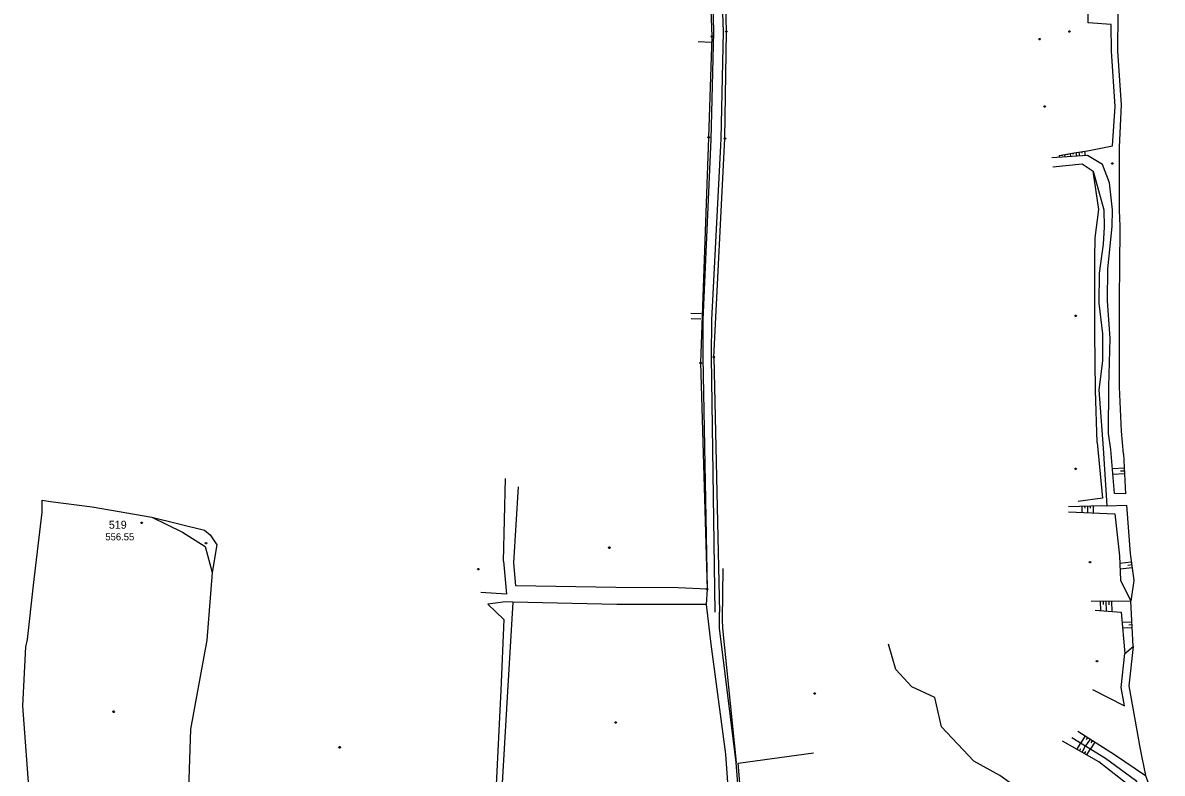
# Model space of a CAD drawing. Extents: x -664960 to -662754, y -993849 to -991145.
# Drawn here: x -664427.2 to -663943.3, y -992059.4 to -991740.8 of the extents above; entities that cross this region are included whole.
import ezdxf

# ---------------------------------------------------------------- set-up
doc = ezdxf.new("R2010")
doc.units = 0
for name, color, linetype in [('Vrstva 1', 7, 'Continuous'), ('Vrstva 12', 7, 'Continuous'), ('Vrstva 13', 7, 'Continuous'), ('Vrstva 18', 7, 'Continuous'), ('Vrstva 27', 7, 'Continuous'), ('Vrstva 28', 7, 'Continuous'), ('Vrstva 6', 7, 'Continuous'), ('Vrstva 63', 7, 'Continuous'), ('Vrstva 8', 7, 'Continuous')]:
    doc.layers.add(name, color=color, linetype=linetype)

msp = doc.modelspace()

# ---------------------------------------------------------------- linework, layer by layer
at = {"layer": 'Vrstva 12'}
msp.add_lwpolyline([(-664087.76, -992082.088), (-664120.622, -992086.914), (-664123.342, -992055.125), (-664091.387, -992050.694)], dxfattribs=at)
at = {"layer": 'Vrstva 13'}
for points in [[(-663993.028, -991776.032), (-663992.848, -991776.332), (-663993.028, -991776.632), (-663993.388, -991776.632), (-663993.568, -991776.332), (-663993.388, -991776.032), (-663993.028, -991776.032)], [(-663964.255, -991800.227), (-663964.075, -991800.527), (-663964.255, -991800.827), (-663964.615, -991800.827), (-663964.795, -991800.527), (-663964.615, -991800.227), (-663964.255, -991800.227)], [(-663979.838, -991864.893), (-663979.658, -991865.193), (-663979.838, -991865.493), (-663980.198, -991865.493), (-663980.378, -991865.193), (-663980.198, -991864.893), (-663979.838, -991864.893)], [(-663979.848, -991929.914), (-663979.668, -991930.214), (-663979.848, -991930.514), (-663980.208, -991930.514), (-663980.388, -991930.214), (-663980.208, -991929.914), (-663979.848, -991929.914)], [(-664349.219, -991961.406), (-664349.039, -991961.706), (-664349.219, -991962.006), (-664349.579, -991962.006), (-664349.759, -991961.706), (-664349.579, -991961.406), (-664349.219, -991961.406)], [(-664177.878, -991963.344), (-664177.698, -991963.644), (-664177.878, -991963.944), (-664178.238, -991963.944), (-664178.418, -991963.644), (-664178.238, -991963.344), (-664177.878, -991963.344)], [(-663973.789, -991969.535), (-663973.609, -991969.835), (-663973.789, -991970.135), (-663974.149, -991970.135), (-663974.329, -991969.835), (-663974.149, -991969.535), (-663973.789, -991969.535)], [(-664233.506, -991972.423), (-664233.326, -991972.723), (-664233.506, -991973.023), (-664233.866, -991973.023), (-664234.046, -991972.723), (-664233.866, -991972.423), (-664233.506, -991972.423)], [(-663970.759, -992011.486), (-663970.579, -992011.786), (-663970.759, -992012.086), (-663971.119, -992012.086), (-663971.299, -992011.786), (-663971.119, -992011.486), (-663970.759, -992011.486)], [(-664090.692, -992025.293), (-664090.512, -992025.593), (-664090.692, -992025.893), (-664091.052, -992025.893), (-664091.232, -992025.593), (-664091.052, -992025.293), (-664090.692, -992025.293)], [(-664388.454, -992032.938), (-664388.274, -992033.238), (-664388.454, -992033.538), (-664388.814, -992033.538), (-664388.994, -992033.238), (-664388.814, -992032.938), (-664388.454, -992032.938)], [(-664175.204, -992037.575), (-664175.024, -992037.875), (-664175.204, -992038.175), (-664175.564, -992038.175), (-664175.744, -992037.875), (-664175.564, -992037.575), (-664175.204, -992037.575)], [(-664292.398, -992048.101), (-664292.218, -992048.401), (-664292.398, -992048.701), (-664292.758, -992048.701), (-664292.938, -992048.401), (-664292.758, -992048.101), (-664292.398, -992048.101)]]:
    msp.add_lwpolyline(points, dxfattribs=at)
at = {"layer": 'Vrstva 18'}
for points in [[(-663995.174, -991747.477), (-663994.994, -991747.777), (-663995.174, -991748.077), (-663995.534, -991748.077), (-663995.714, -991747.777), (-663995.534, -991747.477), (-663995.174, -991747.477)], [(-663982.476, -991744.236), (-663982.296, -991744.536), (-663982.476, -991744.836), (-663982.836, -991744.836), (-663983.016, -991744.536), (-663982.836, -991744.236), (-663982.476, -991744.236)], [(-664136.38, -991980.94), (-664136.2, -991981.24), (-664136.38, -991981.54), (-664136.74, -991981.54), (-664136.92, -991981.24), (-664136.74, -991980.94), (-664136.38, -991980.94)]]:
    msp.add_lwpolyline(points, dxfattribs=at)
at = {"layer": 'Vrstva 27'}
for p, q in [((-664133.69, -991882.79), (-664131.26, -991990.95)), ((-664139.31, -991885.24), (-664136.56, -991981.24))]:
    msp.add_line(p, q, dxfattribs=at)
for points in [[(-664133.76, -991622.74), (-664136.26, -991701.13), (-664134.54, -991746.66), (-664135.91, -991789.46), (-664139.31, -991885.24)], [(-664133.69, -991882.79), (-664128.98, -991790), (-664128.35, -991744.5), (-664129.62, -991693.99), (-664126.2, -991623.19)], [(-664134.36, -991746.36), (-664134.18, -991746.66), (-664134.36, -991746.96), (-664134.72, -991746.96), (-664134.9, -991746.66), (-664134.72, -991746.36), (-664134.36, -991746.36)], [(-664128.17, -991744.2), (-664127.99, -991744.5), (-664128.17, -991744.8), (-664128.53, -991744.8), (-664128.71, -991744.5), (-664128.53, -991744.2), (-664128.17, -991744.2)], [(-664135.73, -991789.16), (-664135.55, -991789.46), (-664135.73, -991789.76), (-664136.09, -991789.76), (-664136.27, -991789.46), (-664136.09, -991789.16), (-664135.73, -991789.16)], [(-664128.8, -991789.7), (-664128.62, -991790), (-664128.8, -991790.3), (-664129.16, -991790.3), (-664129.34, -991790), (-664129.16, -991789.7), (-664128.8, -991789.7)], [(-663965.081, -991921.967), (-663966.071, -991915.134), (-663965.899, -991895.174), (-663965.394, -991874.877), (-663966.498, -991858.814), (-663966.3, -991845.24), (-663964.466, -991827.329), (-663964.397, -991820.302), (-663965.695, -991808.804), (-663968.679, -991800.982), (-663975.044, -991797.204), (-663990.208, -991798.159)], [(-663989.715, -991801.952), (-663977.282, -991800.747), (-663972.626, -991803.762), (-663968.037, -991820.234), (-663967.857, -991827.623), (-663968.372, -991834.776), (-663969.969, -991847.156), (-663970.144, -991859.834), (-663968.66, -991872.81), (-663968.654, -991884.271), (-663970.24, -991896.577), (-663968.403, -991921.366)], [(-664133.51, -991882.49), (-664133.33, -991882.79), (-664133.51, -991883.09), (-664133.87, -991883.09), (-664134.05, -991882.79), (-664133.87, -991882.49), (-664133.51, -991882.49)], [(-664139.13, -991884.94), (-664138.95, -991885.24), (-664139.13, -991885.54), (-664139.49, -991885.54), (-664139.67, -991885.24), (-664139.49, -991884.94), (-664139.13, -991884.94)], [(-663968.403, -991921.366), (-663966.74, -991945.879), (-663958.425, -991945.59)], [(-663958.913, -991940.781), (-663963.592, -991940.621), (-663965.081, -991921.967)], [(-664136.56, -991981.24), (-664136.89, -991987.76), (-664134.9, -992004.59), (-664128.78, -992051.29), (-664125.55, -992095.45), (-664123.48, -992115.18), (-664118.48, -992141.38), (-664113.62, -992159.36), (-664110.38, -992176.55), (-664109.39, -992189.71), (-664111.04, -992229.69), (-664113.75, -992269.61), (-664115.45, -992289.53), (-664116.38, -992290.52)], [(-664136.89, -991987.76), (-664174.87, -991987.75), (-664219.08, -991986.8), (-664222.15, -991986.66), (-664229.67, -991987.66)], [(-664098.79, -992294.95), (-664110.54, -992286.58), (-664108.77, -992270.34), (-664106.52, -992236.03), (-664104.5, -992190.33), (-664105.14, -992175.85), (-664107.23, -992164.98), (-664114.59, -992137.29), (-664118.86, -992115.21), (-664121.07, -992094.42), (-664124.26, -992054.77), (-664131.31, -991997.85), (-664131.26, -991990.95)]]:
    msp.add_lwpolyline(points, dxfattribs=at)
at = {"layer": 'Vrstva 28'}
msp.add_lwpolyline([(-663981.702, -992044.208), (-663967.289, -992052.977), (-663954.558, -992062.267), (-663947.444, -992072.87), (-663943.265, -992100.123)], dxfattribs=at)
at = {"layer": 'Vrstva 6'}
for points in [[(-664133.07, -991990.975), (-664134.652, -991882.772), (-664134.591, -991866.892), (-664130.637, -991790.088), (-664129.603, -991744.621), (-664130.516, -991716.181), (-664131.367, -991701.086), (-664127.809, -991623.225)], [(-664135.382, -991701.086), (-664134.591, -991716.121), (-664133.8, -991744.681), (-664135.017, -991790.329), (-664138.423, -991866.892), (-664138.363, -991882.893), (-664136.56, -991981.24)]]:
    msp.add_lwpolyline(points, dxfattribs=at)
at = {"layer": 'Vrstva 63'}
for p, q in [((-664134.86, -991749.15), (-664140.382, -991748.885)), ((-663985.916, -991796.971), (-663985.864, -991797.273)), ((-663984.733, -991796.767), (-663984.555, -991797.803)), ((-663983.55, -991796.563), (-663983.484, -991796.951)), ((-663982.368, -991796.36), (-663982.145, -991797.651)), ((-663981.185, -991796.156), (-663981.104, -991796.628)), ((-663980.003, -991795.952), (-663979.736, -991797.499)), ((-663978.688, -991795.753), (-663978.441, -991797.418)), ((-663977.501, -991795.577), (-663977.414, -991796.164)), ((-663976.314, -991795.4), (-663976.037, -991797.266)), ((-663987.098, -991797.174), (-663986.964, -991797.954)), ((-664139.12, -991864.38), (-664143.455, -991864.263)), ((-664139.17, -991866.6), (-664143.378, -991866.526)), ((-663963.592, -991940.621), (-663965.081, -991921.967)), ((-663959.715, -991923.798), (-663958.913, -991940.781)), ((-663959.425, -991929.946), (-663964.425, -991930.182)), ((-663959.311, -991932.343), (-663964.234, -991932.576)), ((-663959.368, -991931.145), (-663961.02, -991931.223)), ((-664223.02, -991969.39), (-664222.13, -991934.26)), ((-664218.64, -991970.09), (-664216.66, -991937.78)), ((-663977.419, -991946.033), (-663977.341, -991948.71)), ((-663976.22, -991945.998), (-663976.193, -991946.916)), ((-663975.02, -991945.962), (-663974.937, -991948.801)), ((-663973.821, -991945.927), (-663973.792, -991946.9)), ((-663972.621, -991945.892), (-663972.533, -991948.893)), ((-663958.425, -991945.59), (-663956.862, -991966.165)), ((-663956.862, -991966.165), (-663955.384, -991977.596)), ((-663956.397, -991969.765), (-663961.258, -991970.393)), ((-663956.243, -991970.955), (-663957.899, -991971.169)), ((-663956.089, -991972.145), (-663961.172, -991972.802)), ((-663955.384, -991977.596), (-663956.636, -991986.399)), ((-663969.549, -991986.516), (-663969.515, -991990.316)), ((-663968.35, -991986.506), (-663968.338, -991987.808)), ((-663967.15, -991986.495), (-663967.113, -991990.519)), ((-663965.95, -991986.484), (-663965.937, -991987.861)), ((-663964.75, -991986.473), (-663964.711, -991990.722)), ((-663956.172, -991995.252), (-663960.332, -991995.47)), ((-663956.046, -991997.649), (-663960.12, -991997.863)), ((-663956.109, -991996.451), (-663957.48, -991996.523)), ((-663975.953, -992043.572), (-663977.856, -992046.548)), ((-663979.388, -992049.236), (-663977.856, -992046.548)), ((-663977.302, -992050.424), (-663975.805, -992047.796)), ((-663973.931, -992044.865), (-663975.805, -992047.796)), ((-663974.942, -992044.219), (-663975.571, -992045.202)), ((-663971.909, -992046.158), (-663973.754, -992049.043)), ((-663972.92, -992045.512), (-663973.539, -992046.48)), ((-663978.345, -992049.83), (-663977.841, -992048.945)), ((-663976.26, -992051.018), (-663975.767, -992050.153)), ((-663975.217, -992051.612), (-663973.754, -992049.044))]:
    msp.add_line(p, q, dxfattribs=at)
for points in [[(-663959.715, -991923.798), (-663960.593, -991914.195), (-663961.394, -991895.576), (-663961.372, -991874.837), (-663961.363, -991857.329), (-663961.291, -991844.816), (-663961.073, -991827.104), (-663961.426, -991820.378), (-663961.357, -991810.826), (-663961.455, -991793.652), (-663960.545, -991775.732), (-663962.132, -991752.853), (-663961.949, -991736.817), (-663962.977, -991711.149), (-663963.572, -991697.294), (-663964.386, -991675.576), (-663964.842, -991660.15), (-663964.464, -991648.1), (-663963.049, -991635.434), (-663967.776, -991613.698), (-663970.288, -991592.325), (-663973.672, -991587.46)], [(-663987.098, -991797.174), (-663979.834, -991795.923), (-663974.94, -991795.196), (-663964.388, -991793.101), (-663963.27, -991776.342), (-663964.866, -991752.89), (-663964.975, -991741.576), (-663974.648, -991740.886), (-663974.449, -991710.608), (-663972.188, -991697.495), (-663976.993, -991679.21), (-663979.91, -991660.701), (-663979.251, -991649.053), (-663980.799, -991631.514), (-663983.018, -991616.864), (-663985.679, -991606.194)], [(-663970.918, -991918.967), (-663971.657, -991896.941), (-663971.846, -991872.452), (-663971.903, -991861.736), (-663971.928, -991840.762), (-663971.737, -991832.184), (-663970.231, -991820.155), (-663972.626, -991803.762)], [(-663970.918, -991918.967), (-663968.624, -991942.586), (-663978.986, -991944.017)], [(-664424.04, -992072.86), (-664427.17, -992030.77), (-664425.81, -992005.7), (-664425.19, -992002.6), (-664422.65, -991979.52), (-664418.91, -991948.62), (-664418.92, -991943.43), (-664415.46, -991944.04), (-664397.64, -991946.32), (-664372.33, -991950.72), (-664359.33, -991957.01), (-664349.66, -991963.14), (-664346.68, -991974.16), (-664348.97, -992002.86), (-664355.9, -992040.69), (-664357.02, -992074.72)], [(-663983.027, -991946.197), (-663968.94, -991945.785), (-663966.74, -991945.879)], [(-664372.33, -991950.72), (-664349.94, -991956.16), (-664347.66, -991958.15), (-664344.69, -991962.48), (-664346.68, -991974.16)], [(-663983.1, -991948.49), (-663963.334, -991949.243), (-663961.373, -991967.173), (-663961.007, -991977.463), (-663956.636, -991986.399)], [(-664223.02, -991969.39), (-664221.8, -991983.35), (-664232.67, -991982.6)], [(-664136.56, -991981.24), (-664148.87, -991980.65), (-664175.28, -991980.53), (-664217.75, -991979.88), (-664218.64, -991970.09)], [(-664129.89, -991972.45), (-664130.13, -991994.15), (-664130.07, -991997.79), (-664124.26, -992054.77)], [(-664229.67, -991987.66), (-664222.84, -991994.11), (-664224.09, -992024.18), (-664226.23, -992067.16), (-664227.78, -992112.81)], [(-664219.08, -991986.8), (-664221.33, -992024.66), (-664223.9, -992068.47), (-664222.42, -992113.54), (-664216.91, -992170.19), (-664214.21, -992186.59), (-664211.99, -992218.21), (-664212.61, -992229.72)], [(-663971.718, -991990.13), (-663960.723, -991991.059), (-663959.178, -992008.495), (-663955.63, -992005.604), (-663956.636, -991986.399), (-663973.439, -991986.552)], [(-663993.668, -992073.655), (-664012.262, -992060.304), (-664023.311, -992054.244), (-664037.049, -992039.629), (-664039.796, -992027.226), (-664049.542, -992022.752), (-664056.463, -992015.364), (-664059.529, -992004.564)], [(-663972.893, -992023.891), (-663959.341, -992030.809), (-663960.662, -992022.936), (-663959.178, -992008.495)], [(-663955.63, -992005.604), (-663957.469, -992022.347), (-663952.597, -992049.166), (-663950.399, -992060.402)], [(-663979.157, -992041.523), (-663963.566, -992051.494), (-663950.399, -992060.402), (-663946.03, -992072.343)], [(-663977.818, -992076.971), (-663947.068, -992094.554), (-663950.141, -992074.528), (-663956.408, -992065.276), (-663970.142, -992054.503), (-663985.578, -992045.709)]]:
    msp.add_lwpolyline(points, dxfattribs=at)
at = {"layer": 'Vrstva 8'}
msp.add_lwpolyline([(-664376.52, -991952.84), (-664376.34, -991953.14), (-664376.52, -991953.44), (-664376.88, -991953.44), (-664377.06, -991953.14), (-664376.88, -991952.84), (-664376.52, -991952.84)], dxfattribs=at)

# ---------------------------------------------------------------- texts
at = {"layer": 'Vrstva 1'}
msp.add_text('519', height=3.4, dxfattribs=at).set_placement((-664390.625, -991955.599))
at = {"layer": 'Vrstva 63'}
msp.add_text('556.55', height=3, dxfattribs=at).set_placement((-664392.1, -991960.534))

doc.saveas('drawing.dxf')
